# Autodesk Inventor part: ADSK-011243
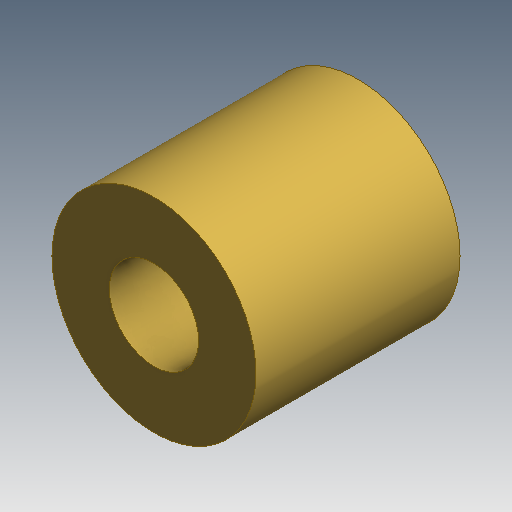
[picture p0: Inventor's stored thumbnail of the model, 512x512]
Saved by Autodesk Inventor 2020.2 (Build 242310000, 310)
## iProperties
Created: 2000-10
Part Number: ADSK-011243
Document SubType Name: Modeling
Designer: wymerj
Material: Générique
Density: 1 g/cm^3
Appearance: Vorgabe
Mass: 83.2552 g
Surface Area: 149.32 cm^2
Volume: 83.2552 cm^3
Control State: 0
Master: False
Checked Out: False
Shininess: 0.0
Length Units: 11272
Angle Units: 11279
Time Units: 11290
Mass Units: 11286
Length Display Precision: 3
Angle Display Precision: 2
Compacted: True
Dimensions: 2x2x2 in
Mass: 0,184 lb
VLT_Material: Generic
Density: 0.0
Volumn: 0.0
Area: 0.0
PropertySet Name: Model Information
Author: wymerj
Revision Number: -
Title: ADSK-011243
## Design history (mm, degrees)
node "Extrusion1" dims "d2" = 50.8, "d3" = 0
node "Extrusion2" dims "d5" = 50.8, "d6" = 0
workaxis "Work Axis1"
workplane "Work Plane1"
node "Solide1"
node "Corps solides"
node "Corps surfaciques"
sketch "Sketch1"
  geometry: C1 r 9.525 at (-0.866, 0) reference; C2 r 25.4 at (-0.866, 0)
  constraints: 1 centre point
  dimensions: "d1" = 50.8 diameter of C2
sketch "Sketch2"
  geometry: C1 r 25.4 at (0, 0) reference; C2 r 11.113 at (0, 0)
  constraints: 1 centre point, 1 coincident
  dimensions: "d4" = 22.225 diameter of C2
other parameters: "d7" = 0
